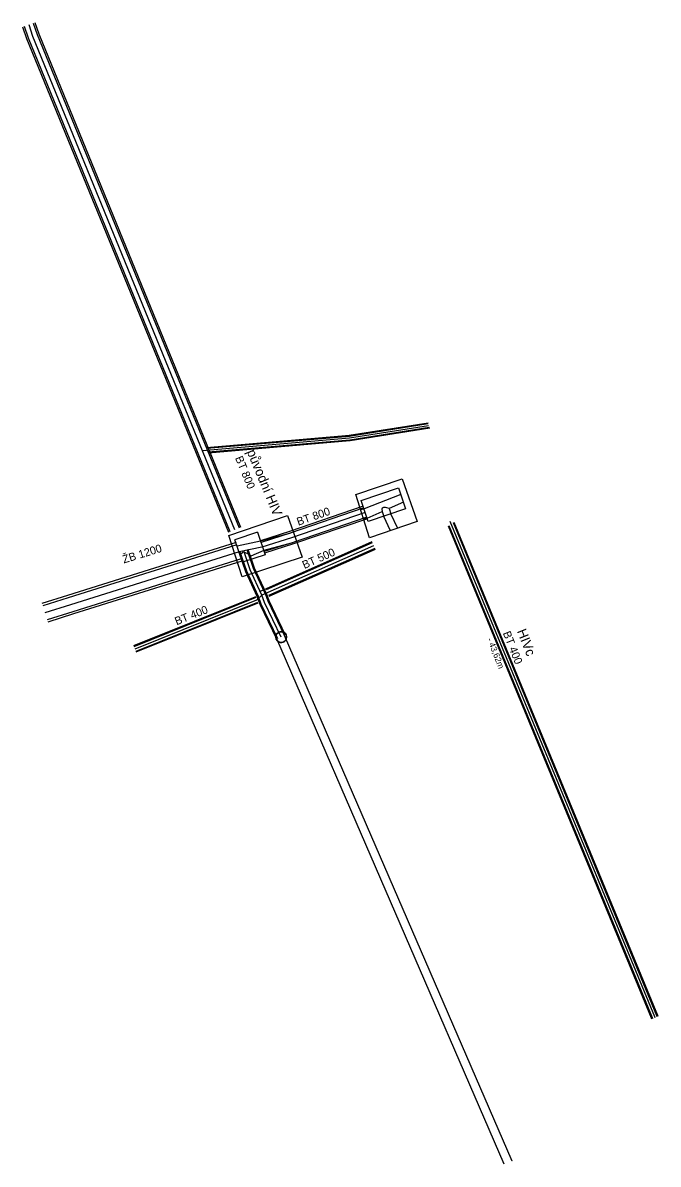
# Model space of a CAD drawing. Extents: x -969087 to -122837, y -1605141 to -636627.
# Drawn here: x -545226.3 to -545159.2, y -1121769.7 to -1121649.2 of the extents above; entities that cross this region are included whole.
import ezdxf

# ---------------------------------------------------------------- set-up
doc = ezdxf.new("R2010")
doc.units = 0
for name, color, linetype in [('Vrstva 14', 7, 'Continuous'), ('Vrstva 2', 7, 'Continuous'), ('Vrstva 5', 7, 'Continuous')]:
    doc.layers.add(name, color=color, linetype=linetype)

# ---------------------------------------------------------------- blocks, each defined once
blk = doc.blocks.new('_U116')
at = {"layer": 'Vrstva 5'}
blk.add_lwpolyline([(-0.0168, -0.0081), (-0.0159, -0.0098), (-0.0147, -0.0113), (-0.0135, -0.0129), (-0.0121, -0.0142), (-0.0105, -0.0154), (-0.0088, -0.0164), (-0.0071, -0.0172), (-0.0052, -0.0179), (-0.0033, -0.0183), (-0.0014, -0.0185), (0.0006, -0.0186), (0.0025, -0.0185), (0.0044, -0.0181), (0.0063, -0.0176), (0.0081, -0.0168), (0.0098, -0.0159), (0.0114, -0.0147), (0.0129, -0.0135), (0.0142, -0.0121), (0.0154, -0.0105), (0.0164, -0.0088), (0.0173, -0.0071), (0.0179, -0.0052), (0.0184, -0.0033), (0.0186, -0.0014), (0.0186, 0.0006), (0.0185, 0.0025), (0.0182, 0.0044), (0.0176, 0.0063), (0.0168, 0.0081), (0.0159, 0.0098), (0.0148, 0.0114), (0.0135, 0.0129), (0.0121, 0.0142), (0.0106, 0.0154), (0.0089, 0.0165), (0.0071, 0.0173), (0.0052, 0.0179), (0.0034, 0.0183), (0.0014, 0.0186), (-0.0005, 0.0187), (-0.0025, 0.0185), (-0.0044, 0.0182), (-0.0063, 0.0176), (-0.0081, 0.0168), (-0.0098, 0.0159), (-0.0114, 0.0148), (-0.0128, 0.0136), (-0.0142, 0.0121), (-0.0154, 0.0105), (-0.0164, 0.0089), (-0.0173, 0.0071), (-0.0179, 0.0053), (-0.0183, 0.0034), (-0.0186, 0.0014), (-0.0186, -0.0006), (-0.0185, -0.0024), (-0.0181, -0.0044), (-0.0175, -0.0063), (-0.0168, -0.0081)], dxfattribs=at)

msp = doc.modelspace()

# ---------------------------------------------------------------- linework, layer by layer
at = {"layer": 'Vrstva 14'}
for points in [[(-545190.53, -1121699.66), (-545186.58, -1121698.33), (-545185.84, -1121700.55), (-545189.78, -1121701.87), (-545190.53, -1121699.66)], [(-545186.34, -1121699.04), (-545190.23, -1121700.54), (-545190.58, -1121700.67)], [(-545186.07, -1121699.85), (-545187.59, -1121700.51), (-545187.4, -1121701.07)], [(-545190.28, -1121701.63), (-545189.9, -1121701.53), (-545188.31, -1121700.83), (-545188.13, -1121701.36)], [(-545187.59, -1121700.5), (-545187.83, -1121700.43), (-545187.97, -1121700.41), (-545188.16, -1121700.41), (-545188.3, -1121700.47), (-545188.37, -1121700.57), (-545188.31, -1121700.83)], [(-545187.42, -1121701.03), (-545186.7, -1121702.59)], [(-545187.44, -1121702.87), (-545188.13, -1121701.35)], [(-545201.47, -1121703.02), (-545203.86, -1121703.82)], [(-545201.47, -1121703.02), (-545200.68, -1121705.39), (-545203.07, -1121706.19), (-545203.86, -1121703.82)], [(-545197.7, -1121703.01), (-545198.11, -1121703.14), (-545201.16, -1121703.95)], [(-545201.16, -1121703.95), (-545203.64, -1121704.48)], [(-545197.35, -1121703.97), (-545197.8, -1121704.13), (-545200.83, -1121704.94), (-545202.19, -1121705.54), (-545202.35, -1121705.41), (-545202.58, -1121705.27), (-545202.87, -1121705.16), (-545203.07, -1121705.13), (-545203.17, -1121705.26), (-545203.27, -1121705.36), (-545203.24, -1121705.55), (-545203.21, -1121705.77), (-545203.16, -1121705.95), (-545203.16, -1121705.94), (-545202.68, -1121707.34), (-545202.56, -1121707.56)]]:
    msp.add_lwpolyline(points, dxfattribs=at)
at = {"layer": 'Vrstva 2'}
for p, q in [((-545183.46, -1121691.5), (-545191.8, -1121692.81)), ((-545183.45, -1121691.59), (-545191.79, -1121692.9)), ((-545183.42, -1121691.78), (-545191.76, -1121693.09)), ((-545183.35, -1121691.97), (-545191.73, -1121693.29)), ((-545183.3, -1121692.05), (-545191.71, -1121693.38)), ((-545191.76, -1121693.09), (-545207.3, -1121694.42)), ((-545191.78, -1121692.81), (-545206.87, -1121694.1)), ((-545191.77, -1121692.9), (-545206.83, -1121694.19)), ((-545191.74, -1121693.29), (-545206.68, -1121694.57)), ((-545191.73, -1121693.38), (-545206.64, -1121694.66))]:
    msp.add_line(p, q, dxfattribs=at)
for points in [[(-545203.24, -1121702.52), (-545224.54, -1121650.45), (-545224.96, -1121649.24)], [(-545204.51, -1121703.04), (-545225.83, -1121650.94), (-545226.26, -1121649.7)], [(-545204.36, -1121702.98), (-545225.67, -1121650.88), (-545226.1, -1121649.64)], [(-545203.88, -1121702.78), (-545225.19, -1121650.7), (-545225.61, -1121649.47)], [(-545203.4, -1121702.59), (-545224.7, -1121650.51), (-545225.12, -1121649.3)], [(-545191.11, -1121699.02), (-545186.2, -1121697.37), (-545184.61, -1121701.88), (-545189.65, -1121703.62), (-545191.11, -1121699.02)], [(-545190.1, -1121700.94), (-545197.88, -1121703.61), (-545201.03, -1121704.61), (-545203.43, -1121705.1)], [(-545190.32, -1121700.28), (-545198.1, -1121702.96), (-545201.17, -1121703.93)], [(-545190.26, -1121700.44), (-545198.04, -1121703.12), (-545201.11, -1121704.09)], [(-545204.51, -1121703.36), (-545198.32, -1121701.27), (-545196.76, -1121705.65), (-545203.1, -1121707.73), (-545204.51, -1121703.36)], [(-545189.93, -1121701.43), (-545197.72, -1121704.1), (-545200.79, -1121705.07)], [(-545189.87, -1121701.59), (-545197.67, -1121704.26), (-545200.73, -1121705.23)], [(-545159.5, -1121754.29), (-545159.54, -1121754.18), (-545181.15, -1121701.88)], [(-545159.26, -1121754.19), (-545159.3, -1121754.08), (-545180.8, -1121702.04)], [(-545159.17, -1121754.15), (-545159.21, -1121754.05), (-545180.72, -1121701.98)], [(-545159.83, -1121754.43), (-545159.87, -1121754.32), (-545181.33, -1121702.39)], [(-545159.74, -1121754.39), (-545159.78, -1121754.28), (-545181.24, -1121702.34)], [(-545203.74, -1121704.12), (-545221.55, -1121709.69), (-545224.24, -1121710.54)], [(-545203.66, -1121704.35), (-545221.47, -1121709.93), (-545224.16, -1121710.78)], [(-545189.41, -1121704.05), (-545201.19, -1121709.26)], [(-545189.23, -1121704.45), (-545201.02, -1121709.65)], [(-545189.36, -1121704.15), (-545200.56, -1121709.1)], [(-545203.43, -1121705.1), (-545221.24, -1121710.67), (-545223.93, -1121711.52)], [(-545203.43, -1121705.1), (-545221.24, -1121710.67), (-545223.93, -1121711.52)], [(-545203.2, -1121705.84), (-545221, -1121711.42), (-545223.69, -1121712.27)], [(-545201.48, -1121709.87), (-545202.73, -1121707.19), (-545203.42, -1121705.16)], [(-545201.37, -1121709.82), (-545202.62, -1121707.14), (-545203.31, -1121705.12)], [(-545201.02, -1121709.66), (-545202.26, -1121707), (-545202.94, -1121705)], [(-545200.67, -1121709.49), (-545201.9, -1121706.85), (-545202.57, -1121704.87)], [(-545200.56, -1121709.44), (-545201.79, -1121706.81), (-545202.46, -1121704.83)], [(-545189.1, -1121704.74), (-545200.33, -1121709.71)], [(-545189.05, -1121704.84), (-545200.29, -1121709.81)], [(-545203.12, -1121706.08), (-545220.93, -1121711.65), (-545223.62, -1121712.5)], [(-545198.52, -1121713.87), (-545200.26, -1121710.26), (-545200.54, -1121709.48)], [(-545214.54, -1121714.99), (-545201.74, -1121709.84), (-545201.69, -1121709.79)], [(-545214.51, -1121715.08), (-545201.69, -1121709.92), (-545201.65, -1121709.89)], [(-545214.41, -1121715.32), (-545201.55, -1121710.15), (-545201.02, -1121709.66)], [(-545214.31, -1121715.56), (-545201.45, -1121710.39)], [(-545214.28, -1121715.65), (-545201.42, -1121710.48)], [(-545199.44, -1121714.31), (-545201.2, -1121710.65), (-545201.5, -1121709.83)], [(-545199.34, -1121714.26), (-545201.09, -1121710.6), (-545201.39, -1121709.79)], [(-545198.98, -1121714.09), (-545200.73, -1121710.45), (-545201.02, -1121709.66)], [(-545198.63, -1121713.92), (-545200.37, -1121710.3), (-545200.65, -1121709.52)], [(-545175.43, -1121769.73), (-545199.45, -1121714.29)], [(-545174.58, -1121769.43), (-545174.59, -1121769.41), (-545198.63, -1121713.93)]]:
    msp.add_lwpolyline(points, dxfattribs=at)
msp.add_circle((-545198.98, -1121714.09), 0.569, dxfattribs=at)

# ---------------------------------------------------------------- block references
at = {"layer": 'Vrstva 2', "xscale": 30.502937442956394, "yscale": 30.502937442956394}
msp.add_blockref('_U116', (-545198.98, -1121714.09), dxfattribs=at)

# ---------------------------------------------------------------- texts
at = {"layer": 'Vrstva 2'}
for s, height, rotation, p in [('BT 800', 0.845, 292.5015, (-545203.87, -1121695.18)), ('původní HIV ', 1.014, 292.5015, (-545202.63, -1121694.51)), ('BT 800', 0.845, 19.1189, (-545197.17, -1121702.34)), ('ŽB 1200 ', 0.845, 17.0591, (-545215.59, -1121706.32)), ('BT 500', 0.845, 24.0148, (-545196.53, -1121706.91)), ('BT 400', 0.845, 21.4976, (-545210.02, -1121712.85)), (' - 43,62m  ', 0.65, 291.6312, (-545177.35, -1121714.09)), ('BT 400', 0.845, 291.6312, (-545175.59, -1121713.66)), ('HIVc', 1.014, 291.6312, (-545174.1, -1121713.46))]:
    msp.add_text(s, height=height, rotation=rotation, dxfattribs=at).set_placement(p)

doc.saveas('drawing.dxf')
